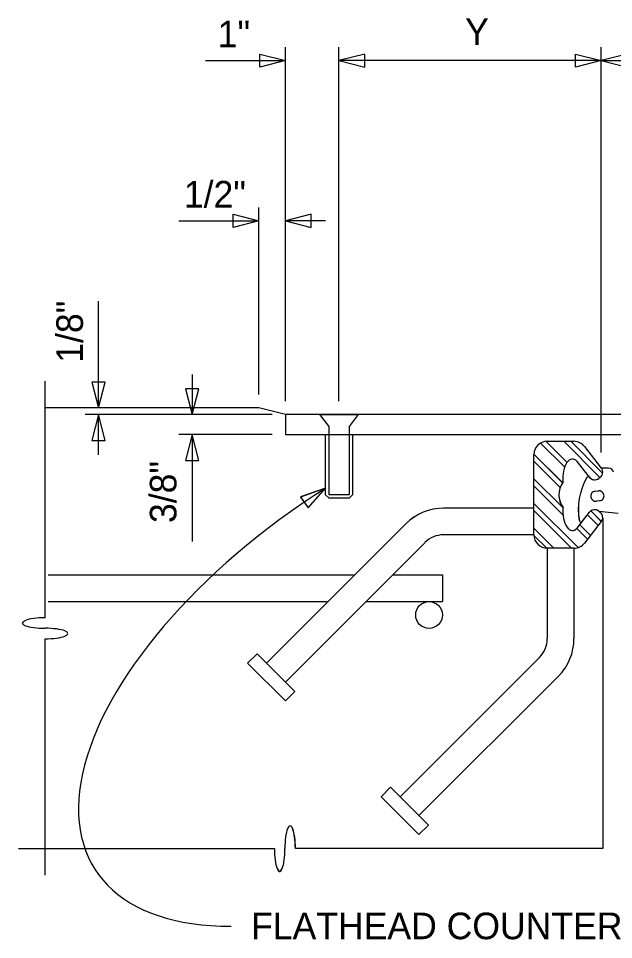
# Model space of a CAD drawing. Extents: x 19590 to 20151, y 19944 to 20103.
# Drawn here: x 19880.48 to 19891.62, y 20061.56 to 20078.8 of the extents above; entities that cross this region are included whole.
import ezdxf

# ---------------------------------------------------------------- set-up
doc = ezdxf.new("R2010")
doc.units = 0
for name, color, linetype in [('DETAIL_PR', 7, 'Continuous'), ('Level 1', 7, 'Continuous'), ('MT_PAVT_MRKGS_EX', 7, 'Continuous'), ('MT_PAVT_MRKGS_EX_REF', 7, 'Continuous'), ('PAVT_MRKGS_QUANT', 7, 'Continuous')]:
    doc.layers.add(name, color=color, linetype=linetype)

# ---------------------------------------------------------------- blocks, each defined once
blk = doc.blocks.new('BRE')
at = {"layer": 'DETAIL_PR'}
for centre, ratio, start_param, end_param in [((0, 0.098), 0.230206, 4.712389, 7.853982), ((0, -0.098), 0.230204, 1.570796, 4.712389)]:
    blk.add_ellipse(centre, major_axis=(-0.427, 0), ratio=ratio, start_param=start_param, end_param=end_param, dxfattribs=at)
blk = doc.blocks.new('EJ3H')
at = {"layer": 'MT_PAVT_MRKGS_EX'}
for p, q in [((73.359, -24.597), (69.359, -24.597)), ((73.859, -24.722), (73.359, -24.597)), ((86.234, -24.722), (73.859, -24.722)), ((73.859, -24.722), (73.859, -25.097)), ((74.672, -24.945), (74.501, -24.722)), ((74.501, -24.722), (75.218, -24.722)), ((75.218, -24.722), (75.047, -24.945)), ((74.672, -26.222), (74.672, -24.945)), ((75.047, -24.945), (75.047, -26.222)), ((73.859, -25.097), (86.359, -25.097)), ((74.609, -26.222), (74.609, -25.097)), ((75.109, -25.097), (75.109, -26.222)), ((78.633, -25.255), (79.083, -25.705)), ((78.733, -25.222), (79.127, -25.616)), ((78.757, -25.222), (79.257, -25.222)), ((79.064, -25.222), (79.742, -25.9)), ((79.197, -25.222), (79.793, -25.818)), ((79.454, -25.319), (79.768, -25.722)), ((78.507, -25.46), (79.042, -25.996)), ((78.507, -26.972), (78.507, -25.472)), ((78.507, -25.593), (78.999, -26.085)), ((79.546, -25.895), (79.315, -25.599)), ((79.905, -25.722), (79.768, -25.722)), ((78.507, -25.922), (79.046, -26.461)), ((79.746, -25.898), (79.721, -25.917)), ((79.746, -25.898), (79.721, -25.917)), ((78.507, -26.054), (79.051, -26.599)), ((79.65, -26.157), (79.712, -26.148)), ((74.609, -26.222), (74.672, -26.285)), ((75.047, -26.222), (74.672, -26.222)), ((75.047, -26.285), (74.672, -26.285)), ((75.109, -26.222), (75.047, -26.285)), ((79.737, -26.334), (79.675, -26.342)), ((78.507, -26.472), (76.817, -26.472)), ((78.507, -26.386), (79.332, -27.211)), ((78.507, -26.518), (79.211, -27.222)), ((79.315, -26.846), (79.546, -26.55)), ((79.412, -26.721), (79.546, -26.55)), ((79.571, -26.525), (79.768, -26.722)), ((79.721, -26.528), (79.746, -26.547)), ((79.721, -26.528), (80.082, -26.565)), ((79.768, -26.722), (79.454, -27.126)), ((79.51, -26.596), (79.71, -26.796)), ((79.794, -26.652), (79.794, -32.844)), ((76.11, -26.765), (73.501, -29.374)), ((78.507, -26.85), (78.879, -27.222)), ((79.308, -26.856), (79.508, -27.056)), ((79.365, -26.782), (79.565, -26.983)), ((78.507, -26.972), (76.817, -26.972)), ((78.507, -26.982), (78.747, -27.222)), ((76.464, -27.119), (73.855, -29.728)), ((78.757, -27.222), (78.757, -28.912)), ((79.257, -27.222), (78.757, -27.222)), ((79.257, -27.222), (79.257, -28.912)), ((69.414, -27.722), (75.153, -27.722)), ((75.86, -27.722), (76.794, -27.722)), ((76.794, -27.722), (76.794, -28.222)), ((69.414, -28.222), (74.653, -28.222)), ((75.36, -28.222), (76.794, -28.222)), ((73.325, -29.197), (73.148, -29.374)), ((73.325, -29.197), (74.032, -29.904)), ((78.61, -29.265), (76.001, -31.874)), ((73.148, -29.374), (73.855, -30.081)), ((78.964, -29.619), (76.355, -32.228)), ((74.032, -29.904), (73.855, -30.081)), ((75.825, -31.697), (75.648, -31.874)), ((75.825, -31.697), (76.532, -32.404)), ((75.648, -31.874), (76.355, -32.581)), ((76.532, -32.404), (76.355, -32.581))]:
    blk.add_line(p, q, dxfattribs=at)
blk.add_circle((76.544, -28.472), 0.25, dxfattribs=at)
for centre, radius, start, end in [((78.757, -25.472), 0.25, 90, 180), ((79.257, -25.472), 0.25, 37.857, 90), ((79.669, -25.799), 0.125, 307.857, 37.857), ((79.669, -25.799), 0.125, 307.857, 37.857), ((79.905, -25.816), 0.0938, 9.7762, 90), ((79.394, -26.222), 0.419, 146.3205, 214.9742), ((80.562, -26.499), 1.224, 150.7366, 189.8297), ((79.522, -25.916), 0.0312, 38.6221, 150.7366), ((79.644, -25.818), 0.125, 217.857, 307.857), ((79.644, -25.818), 0.125, 218.6221, 307.857), ((79.663, -26.25), 0.0938, 97.5995, 189.7762), ((79.725, -26.241), 0.0938, 9.7762, 97.5995), ((79.663, -26.25), 0.0938, 189.7762, 277.5995), ((79.725, -26.241), 0.0937, 277.5995, 9.7762), ((76.817, -27.472), 1, 90, 135), ((79.644, -26.627), 0.125, 52.143, 142.143), ((79.644, -26.627), 0.125, 52.143, 142.143), ((79.669, -26.646), 0.125, 322.143, 52.143), ((79.388, -26.702), 0.0312, 189.8297, 322.143), ((76.817, -27.472), 0.5, 90, 135), ((78.757, -26.972), 0.25, 180, 270), ((79.257, -26.972), 0.25, 270, 322.143), ((78.257, -28.912), 0.5, 315, 360), ((78.257, -28.912), 1, 315, 0)]:
    blk.add_arc(centre, radius, start, end, dxfattribs=at)
for centre, major_axis, start_param, end_param in [((79.24, -25.979), (-0.016, 0.425), 5.802216, 7.862347), ((79.24, -26.466), (0.016, 0.425), 1.562431, 3.622562)]:
    blk.add_ellipse(centre, major_axis=major_axis, ratio=0.457019, start_param=start_param, end_param=end_param, dxfattribs=at)
at = {"layer": 'MT_PAVT_MRKGS_EX_REF'}
for p, q in [((73.859, -24.472), (73.859, -17.847)), ((74.859, -24.472), (74.859, -17.847)), ((79.768, -25.43), (79.768, -17.847)), ((73.377, -17.973), (73.859, -18.097)), ((73.377, -18.222), (73.377, -17.973)), ((73.859, -18.097), (73.377, -18.222)), ((75.341, -17.973), (74.859, -18.097)), ((79.768, -18.097), (74.859, -18.097)), ((74.859, -18.097), (75.341, -18.222)), ((75.341, -18.222), (75.341, -17.973)), ((79.286, -17.973), (79.768, -18.097)), ((79.286, -18.222), (79.286, -17.973)), ((79.768, -18.097), (79.286, -18.222)), ((80.249, -17.973), (79.768, -18.097)), ((79.768, -18.097), (81.938, -18.097)), ((79.768, -18.097), (80.249, -18.222)), ((73.359, -24.347), (73.359, -20.847)), ((72.877, -20.973), (73.359, -21.097)), ((72.877, -21.222), (72.877, -20.973)), ((74.341, -20.973), (73.859, -21.097)), ((74.341, -21.222), (74.341, -20.973)), ((73.359, -21.097), (72.877, -21.222)), ((73.859, -21.097), (74.341, -21.222)), ((69.359, -28.524), (69.359, -24.097)), ((70.235, -24.116), (70.359, -24.597)), ((70.484, -24.116), (70.235, -24.116)), ((70.359, -24.597), (70.484, -24.116)), ((71.985, -24.241), (72.109, -24.722)), ((72.234, -24.241), (71.985, -24.241)), ((72.109, -24.722), (72.234, -24.241)), ((73.609, -24.722), (70.109, -24.722)), ((70.359, -24.722), (70.235, -25.204)), ((70.484, -25.204), (70.359, -24.722)), ((73.609, -25.097), (71.859, -25.097)), ((72.109, -25.097), (71.985, -25.579)), ((72.234, -25.579), (72.109, -25.097)), ((70.235, -25.204), (70.484, -25.204)), ((71.985, -25.579), (72.234, -25.579)), ((74.609, -26.096), (74.141, -26.264)), ((74.28, -26.469), (74.609, -26.096)), ((74.141, -26.264), (74.28, -26.469)), ((69.359, -33.344), (69.359, -28.917)), ((68.859, -32.844), (73.65, -32.844)), ((79.794, -32.844), (74.043, -32.844))]:
    blk.add_line(p, q, dxfattribs=at)
blk.add_ellipse((76.594, -29.219), major_axis=(6.306, 4.007), ratio=0.495228, start_param=1.570796, end_param=3.803242, dxfattribs=at)
at = {"layer": 'PAVT_MRKGS_QUANT'}
for p, q in [((72.359, -18.097), (73.859, -18.097)), ((71.859, -21.097), (73.359, -21.097)), ((74.609, -21.097), (73.859, -21.097)), ((70.359, -24.597), (70.359, -22.597)), ((72.109, -23.972), (72.109, -24.722)), ((70.359, -25.472), (70.359, -24.722)), ((72.109, -25.097), (72.109, -27.097))]:
    blk.add_line(p, q, dxfattribs=at)
for p, rotation in [((69.359, -28.721), 180), ((73.846, -32.844), 90)]:
    blk.add_blockref('BRE', p, dxfattribs=dict(at, rotation=rotation))
at = {"layer": 'MT_PAVT_MRKGS_EX_REF'}
for s, height, p in [('1"', 0.4976, (72.589, -17.846)), ('Y', 0.498, (77.219, -17.805)), ('1/2"', 0.4976, (71.956, -20.846)), ('FLATHEAD COUNTERSUNK', 0.49762, (73.213, -34.54))]:
    blk.add_text(s, height=height, dxfattribs=at).set_placement(p)
for s, p in [('1/8"', (70.066, -23.751)), ('3/8"', (71.816, -26.751))]:
    blk.add_text(s, height=0.4976, rotation=90, dxfattribs=at).set_placement(p)

msp = doc.modelspace()

# ---------------------------------------------------------------- linework, layer by layer
at = {"layer": 'MT_PAVT_MRKGS_EX'}
for p, q in [((19884.983, 20071.509), (19880.983, 20071.509)), ((19885.483, 20071.384), (19884.983, 20071.509)), ((19897.858, 20071.384), (19885.483, 20071.384)), ((19885.483, 20071.384), (19885.483, 20071.009)), ((19886.296, 20071.161), (19886.125, 20071.384)), ((19886.125, 20071.384), (19886.842, 20071.384)), ((19886.842, 20071.384), (19886.671, 20071.161)), ((19886.296, 20069.884), (19886.296, 20071.161)), ((19886.671, 20071.161), (19886.671, 20069.884)), ((19885.483, 20071.009), (19897.983, 20071.009)), ((19886.233, 20069.884), (19886.233, 20071.009)), ((19886.733, 20071.009), (19886.733, 20069.884)), ((19890.257, 20070.851), (19890.707, 20070.401)), ((19890.357, 20070.884), (19890.751, 20070.49)), ((19890.381, 20070.884), (19890.881, 20070.884)), ((19890.689, 20070.884), (19891.367, 20070.206)), ((19890.821, 20070.884), (19891.417, 20070.288)), ((19890.131, 20070.646), (19890.666, 20070.111)), ((19890.131, 20069.134), (19890.131, 20070.634)), ((19891.078, 20070.787), (19891.392, 20070.384)), ((19890.131, 20070.513), (19890.623, 20070.021)), ((19891.17, 20070.211), (19890.939, 20070.508)), ((19891.529, 20070.384), (19891.392, 20070.384)), ((19890.131, 20070.184), (19890.67, 20069.646)), ((19891.37, 20070.208), (19891.345, 20070.189)), ((19891.37, 20070.208), (19891.345, 20070.189)), ((19890.131, 20070.052), (19890.675, 20069.507)), ((19891.275, 20069.95), (19891.337, 20069.958)), ((19886.233, 20069.884), (19886.296, 20069.821)), ((19886.671, 20069.884), (19886.296, 20069.884)), ((19886.671, 20069.821), (19886.296, 20069.821)), ((19886.733, 20069.884), (19886.671, 20069.821)), ((19891.361, 20069.772), (19891.299, 20069.764)), ((19890.131, 20069.634), (19888.442, 20069.634)), ((19890.131, 20069.72), (19890.956, 20068.895)), ((19890.131, 20069.588), (19890.835, 20068.884)), ((19890.939, 20069.26), (19891.17, 20069.556)), ((19891.036, 20069.385), (19891.17, 20069.556)), ((19891.134, 20069.51), (19891.335, 20069.31)), ((19891.196, 20069.581), (19891.393, 20069.384)), ((19891.345, 20069.578), (19891.37, 20069.559)), ((19891.345, 20069.578), (19891.706, 20069.541)), ((19891.418, 20069.454), (19891.418, 20063.262)), ((19887.735, 20069.341), (19885.126, 20066.732)), ((19890.131, 20069.256), (19890.504, 20068.884)), ((19890.989, 20069.324), (19891.19, 20069.123)), ((19891.392, 20069.384), (19891.078, 20068.98)), ((19890.131, 20069.134), (19888.442, 20069.134)), ((19890.131, 20069.124), (19890.371, 20068.884)), ((19890.932, 20069.251), (19891.133, 20069.05)), ((19888.088, 20068.987), (19885.479, 20066.378)), ((19890.381, 20068.884), (19890.381, 20067.194)), ((19890.881, 20068.884), (19890.381, 20068.884)), ((19890.881, 20068.884), (19890.881, 20067.194)), ((19881.038, 20068.384), (19886.777, 20068.384)), ((19887.485, 20068.384), (19888.418, 20068.384)), ((19888.418, 20068.384), (19888.418, 20067.884)), ((19881.038, 20067.884), (19886.277, 20067.884)), ((19886.985, 20067.884), (19888.418, 20067.884)), ((19884.949, 20066.909), (19884.772, 20066.732)), ((19884.949, 20066.909), (19885.656, 20066.202)), ((19890.235, 20066.841), (19887.626, 20064.232)), ((19884.772, 20066.732), (19885.479, 20066.025)), ((19890.588, 20066.487), (19887.979, 20063.878)), ((19885.656, 20066.202), (19885.479, 20066.025)), ((19887.449, 20064.409), (19887.272, 20064.232)), ((19887.449, 20064.409), (19888.156, 20063.702)), ((19887.272, 20064.232), (19887.979, 20063.525)), ((19888.156, 20063.702), (19887.979, 20063.525))]:
    msp.add_line(p, q, dxfattribs=at)
msp.add_circle((19888.168, 20067.634), 0.25, dxfattribs=at)
for centre, radius, start, end in [((19890.381, 20070.634), 0.25, 90, 180), ((19890.881, 20070.634), 0.25, 37.857, 90), ((19891.293, 20070.307), 0.125, 307.857, 37.857), ((19891.293, 20070.307), 0.125, 307.857, 37.857), ((19891.529, 20070.29), 0.0938, 9.7762, 90), ((19891.019, 20069.884), 0.419, 146.3205, 214.9742), ((19892.187, 20069.607), 1.224, 150.7366, 189.8297), ((19891.146, 20070.19), 0.0312, 38.6221, 150.7366), ((19891.269, 20070.288), 0.125, 217.857, 307.857), ((19891.269, 20070.288), 0.125, 218.6221, 307.857), ((19891.287, 20069.857), 0.0938, 97.5995, 189.7762), ((19891.349, 20069.865), 0.0938, 9.7762, 97.5995), ((19891.287, 20069.857), 0.0938, 189.7762, 277.5995), ((19891.349, 20069.865), 0.0937, 277.5995, 9.7762), ((19888.442, 20068.634), 1, 90, 135), ((19891.269, 20069.48), 0.125, 52.143, 142.143), ((19891.269, 20069.48), 0.125, 52.143, 142.143), ((19891.293, 20069.46), 0.125, 322.143, 52.143), ((19891.012, 20069.404), 0.0312, 189.8297, 322.143), ((19888.442, 20068.634), 0.5, 90, 135), ((19890.381, 20069.134), 0.25, 180, 270), ((19890.881, 20069.134), 0.25, 270, 322.143), ((19889.881, 20067.194), 0.5, 315, 360), ((19889.881, 20067.194), 1, 315, 0)]:
    msp.add_arc(centre, radius, start, end, dxfattribs=at)
for centre, major_axis, start_param, end_param in [((19890.864, 20070.127), (-0.016, 0.425), 5.802216, 7.862347), ((19890.864, 20069.64), (0.016, 0.425), 1.562431, 3.622562)]:
    msp.add_ellipse(centre, major_axis=major_axis, ratio=0.457019, start_param=start_param, end_param=end_param, dxfattribs=at)
at = {"layer": 'MT_PAVT_MRKGS_EX_REF'}
for p, q in [((19885.483, 20071.634), (19885.483, 20078.259)), ((19886.483, 20071.634), (19886.483, 20078.259)), ((19891.392, 20070.676), (19891.392, 20078.259)), ((19885.002, 20078.133), (19885.483, 20078.009)), ((19885.002, 20077.884), (19885.002, 20078.133)), ((19886.965, 20078.133), (19886.483, 20078.009)), ((19886.965, 20077.884), (19886.965, 20078.133)), ((19890.91, 20078.133), (19891.392, 20078.009)), ((19890.91, 20077.884), (19890.91, 20078.133)), ((19891.874, 20078.133), (19891.392, 20078.009)), ((19885.483, 20078.009), (19885.002, 20077.884)), ((19891.392, 20078.009), (19886.483, 20078.009)), ((19886.483, 20078.009), (19886.965, 20077.884)), ((19891.392, 20078.009), (19890.91, 20077.884)), ((19891.392, 20078.009), (19893.562, 20078.009)), ((19891.392, 20078.009), (19891.874, 20077.884)), ((19884.502, 20075.133), (19884.983, 20075.009)), ((19884.502, 20074.884), (19884.502, 20075.133)), ((19884.983, 20071.759), (19884.983, 20075.259)), ((19885.965, 20075.133), (19885.483, 20075.009)), ((19885.965, 20074.884), (19885.965, 20075.133)), ((19884.983, 20075.009), (19884.502, 20074.884)), ((19885.483, 20075.009), (19885.965, 20074.884)), ((19880.983, 20067.582), (19880.983, 20072.009)), ((19881.859, 20071.991), (19881.983, 20071.509)), ((19882.108, 20071.991), (19881.859, 20071.991)), ((19881.983, 20071.509), (19882.108, 20071.991)), ((19883.609, 20071.866), (19883.733, 20071.384)), ((19883.858, 20071.866), (19883.609, 20071.866)), ((19883.733, 20071.384), (19883.858, 20071.866)), ((19885.233, 20071.384), (19881.733, 20071.384)), ((19881.983, 20071.384), (19881.859, 20070.902)), ((19882.108, 20070.902), (19881.983, 20071.384)), ((19885.233, 20071.009), (19883.483, 20071.009)), ((19883.733, 20071.009), (19883.609, 20070.527)), ((19883.858, 20070.527), (19883.733, 20071.009)), ((19881.859, 20070.902), (19882.108, 20070.902)), ((19883.609, 20070.527), (19883.858, 20070.527)), ((19886.233, 20070.01), (19885.765, 20069.843)), ((19885.905, 20069.637), (19886.233, 20070.01)), ((19885.765, 20069.843), (19885.905, 20069.637)), ((19880.983, 20062.762), (19880.983, 20067.189)), ((19880.483, 20063.262), (19885.274, 20063.262)), ((19891.418, 20063.262), (19885.667, 20063.262))]:
    msp.add_line(p, q, dxfattribs=at)
msp.add_ellipse((19888.218, 20066.887), major_axis=(6.306, 4.007), ratio=0.495228, start_param=1.570796, end_param=3.803242, dxfattribs=at)
at = {"layer": 'PAVT_MRKGS_QUANT'}
for p, q in [((19883.983, 20078.009), (19885.483, 20078.009)), ((19883.483, 20075.009), (19884.983, 20075.009)), ((19886.233, 20075.009), (19885.483, 20075.009)), ((19881.983, 20071.509), (19881.983, 20073.509)), ((19883.733, 20072.134), (19883.733, 20071.384)), ((19881.983, 20070.634), (19881.983, 20071.384)), ((19883.733, 20071.009), (19883.733, 20069.009))]:
    msp.add_line(p, q, dxfattribs=at)

# ---------------------------------------------------------------- block references
at = {"layer": 'Level 1'}
msp.add_blockref('EJ3H', (19811.624, 20096.106), dxfattribs=at)
at = {"layer": 'PAVT_MRKGS_QUANT'}
for p, rotation in [((19880.984, 20067.385), 180), ((19885.471, 20063.262), 90)]:
    msp.add_blockref('BRE', p, dxfattribs=dict(at, rotation=rotation))

# ---------------------------------------------------------------- texts
at = {"layer": 'MT_PAVT_MRKGS_EX_REF'}
for s, height, p in [('1"', 0.4976, (19884.213, 20078.26)), ('Y', 0.498, (19888.843, 20078.302)), ('1/2"', 0.4976, (19883.58, 20075.26)), ('FLATHEAD COUNTERSUNK', 0.49762, (19884.838, 20061.566))]:
    msp.add_text(s, height=height, dxfattribs=at).set_placement(p)
for s, p in [('1/8"', (19881.691, 20072.355)), ('3/8"', (19883.441, 20069.355))]:
    msp.add_text(s, height=0.4976, rotation=90, dxfattribs=at).set_placement(p)

doc.saveas('drawing.dxf')
